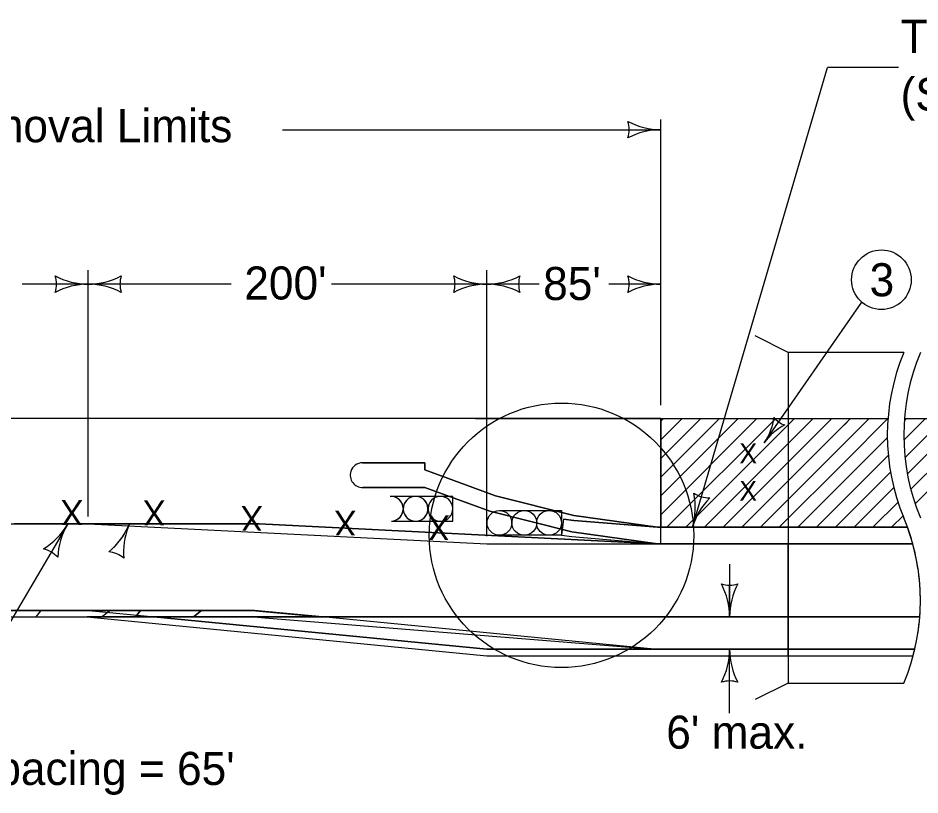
# Model space of a CAD drawing. Extents: x 10133 to 2270741, y 5363 to 1733450.
# Drawn here: x 26557 to 27102, y 11487 to 11957 of the extents above; entities that cross this region are included whole.
import ezdxf

# ---------------------------------------------------------------- set-up
doc = ezdxf.new("R2010")
doc.units = 0
for name, color, linetype in [('dsnNonPlotable', 7, 'Continuous'), ('dsnShtPlotShapeBatchPrint', 7, 'Continuous'), ('dsnStdBlockModified', 7, 'Continuous'), ('dsnStdBorder', 7, 'Continuous'), ('Level 12', 7, 'Continuous'), ('Level 2', 7, 'Continuous')]:
    doc.layers.add(name, color=color, linetype=linetype)

# ---------------------------------------------------------------- blocks, each defined once
blk = doc.blocks.new('LT')
at = {"layer": 'dsnStdBorder'}
for centre, radius, start, end in [((-3.564, 0), 1.642, 342.26665, 17.73335), ((0, 4.25), 4.25, 241.92751, 270), ((0, -4.25), 4.25, 90, 118.07249)]:
    blk.add_arc(centre, radius, start, end, dxfattribs=at)

msp = doc.modelspace()

# ---------------------------------------------------------------- linework, layer by layer
at = {"layer": 'dsnNonPlotable'}
for p, q in [((27022.24, 11754.35), (27002.24, 11764.35)), ((26450.8, 11650.61), (26598.99, 11650.61)), ((26598.99, 11650.61), (26840.04, 11638.61)), ((26943.35, 11648.61), (27094.47, 11648.61)), ((26840.04, 11638.61), (26943.35, 11638.61)), ((27097.65, 11638.61), (26943.35, 11638.61)), ((26598.36, 11594.35), (26924.2, 11594.35)), ((26924.2, 11594.35), (27101.86, 11594.35)), ((26840.04, 11574.84), (27098.85, 11574.84)), ((27022.24, 11554.35), (27002.24, 11544.35))]:
    msp.add_line(p, q, dxfattribs=at)
for points in [[(27092.24, 11754.35), (27022.24, 11754.35), (27022.24, 11554.35), (27092.24, 11554.35)], [(26886.47, 11653.59), (26885.2, 11643.75), (26885.2, 11643.75)], [(26886.47, 11653.59), (26892.7, 11652.78), (26943.35, 11648.61)], [(26885.2, 11643.75), (26891.43, 11642.94), (26943.35, 11638.61)]]:
    msp.add_lwpolyline(points, dxfattribs=at)
for centre, start, end in [((27212.24, 11704.35), 157.3801, 202.6199), ((27222.24, 11704.35), 157.3801, 202.6199), ((26972.24, 11604.35), 337.3801, 22.6199)]:
    msp.add_arc(centre, 130, start, end, dxfattribs=at)
msp.add_open_spline([(26333.01, 11598.33), (26597.17, 11598.33)], degree=1, dxfattribs=at)
at = {"layer": 'dsnShtPlotShapeBatchPrint'}
msp.add_circle((27078.68, 11798.29), 18, dxfattribs=at)
at = {"layer": 'dsnStdBlockModified'}
for p, q in [((26847.69, 11658.75), (26885.2, 11658.75)), ((26885.2, 11658.75), (26885.2, 11643.75)), ((26885.2, 11643.75), (26847.69, 11643.75))]:
    msp.add_line(p, q, dxfattribs=at)
for centre in [(26847.69, 11651.25), (26847.69, 11651.25), (26862.7, 11651.25), (26862.7, 11651.25), (26877.7, 11651.25), (26877.7, 11651.25)]:
    msp.add_circle(centre, 7.5, dxfattribs=at)
at = {"layer": 'dsnStdBorder'}
for p, q in [((26945.31, 11712.79), (26946.86, 11714.35)), ((26945.31, 11701.47), (26958.18, 11714.35)), ((26945.31, 11690.16), (26969.49, 11714.35)), ((26945.31, 11678.85), (26980.81, 11714.35)), ((26945.31, 11667.53), (26992.12, 11714.35)), ((26945.31, 11656.22), (27003.43, 11714.35)), ((26945.31, 11714.35), (26945.31, 11648.61)), ((26949.01, 11648.61), (27014.75, 11714.35)), ((26960.33, 11648.61), (27026.06, 11714.35)), ((26971.64, 11648.61), (27037.37, 11714.35)), ((26982.95, 11648.61), (27048.69, 11714.35)), ((26994.27, 11648.61), (27060, 11714.35)), ((27005.58, 11648.61), (27071.31, 11714.35)), ((27056.08, 11710.38), (27060.04, 11714.35)), ((27056.86, 11688.58), (27082.63, 11714.35)), ((27092.28, 11701.37), (27105.26, 11714.35)), ((27092.53, 11712.93), (27093.94, 11714.35)), ((27092.96, 11690.73), (27116.57, 11714.35)), ((27094.38, 11680.85), (27127.88, 11714.35)), ((27096.44, 11671.59), (27139.2, 11714.35)), ((27099.04, 11662.87), (27150.51, 11714.35)), ((27028.21, 11648.61), (27082.25, 11702.66)), ((27039.52, 11648.61), (27082.84, 11691.93)), ((27016.89, 11648.61), (27056.86, 11688.58)), ((27050.84, 11648.61), (27084.18, 11681.96)), ((27062.15, 11648.61), (27086.17, 11672.64)), ((27073.46, 11648.61), (27088.71, 11663.86)), ((27084.78, 11648.61), (27091.74, 11655.57)), ((26840.04, 11574.84), (26597.17, 11598.33))]:
    msp.add_line(p, q, dxfattribs=at)
for centre, radius in [((26885.2, 11643.75), 80), ((26847.69, 11651.25), 7.5), ((26862.7, 11651.25), 7.5), ((26877.7, 11651.25), 7.5)]:
    msp.add_circle(centre, radius, dxfattribs=at)
at = {"layer": 'Level 12'}
for p, q in [((26964.39, 11648.61), (27046.16, 11926.65)), ((27089, 11926.65), (27046.16, 11926.65)), ((26945.31, 11722.35), (26945.31, 11895.11)), ((26716.55, 11889.05), (26945.31, 11889.05)), ((26598.99, 11655.04), (26598.99, 11804.14)), ((26840.04, 11643.16), (26840.04, 11804.14)), ((26598.99, 11795.63), (26559, 11795.63)), ((26685.41, 11795.63), (26598.99, 11795.63)), ((26840.04, 11795.63), (26746.15, 11795.63)), ((26871.61, 11795.63), (26840.04, 11795.63)), ((26945.31, 11795.63), (26913.74, 11795.63)), ((27007.84, 11699.63), (27066.8, 11784.77)), ((26586.37, 11650.21), (26499.17, 11502.16)), ((26986.89, 11626.35), (26986.89, 11594.35)), ((26976.07, 11594.35), (26994.89, 11594.35)), ((26977.08, 11574.84), (26994.89, 11574.84)), ((26986.89, 11536.08), (26986.89, 11574.84))]:
    msp.add_line(p, q, dxfattribs=at)
for centre, radius, start, end in [((26909.67, 11889.05), 16.42, 342.2666, 17.7334), ((26945.31, 11931.55), 42.5, 241.9275, 270), ((26945.31, 11846.55), 42.5, 90, 118.0725), ((26563.35, 11795.63), 16.42, 342.2666, 17.7334), ((26598.99, 11838.13), 42.5, 241.9275, 270), ((26598.99, 11838.13), 42.5, 270, 298.0725), ((26634.62, 11795.63), 16.42, 162.2666, 197.7334), ((26804.4, 11795.63), 16.42, 342.2666, 17.7334), ((26840.04, 11838.13), 42.5, 241.9275, 270), ((26840.04, 11838.13), 42.5, 270, 298.0725), ((26875.68, 11795.63), 16.42, 162.2666, 197.7334), ((26909.67, 11795.63), 16.42, 342.2666, 17.7334), ((26945.31, 11838.13), 42.5, 241.9275, 270), ((26598.99, 11753.13), 42.5, 90, 118.0725), ((26598.99, 11753.13), 42.5, 61.9275, 90), ((26840.04, 11753.13), 42.5, 90, 118.0725), ((26840.04, 11753.13), 42.5, 61.9275, 90), ((26945.31, 11753.13), 42.5, 90, 118.0725), ((26923.62, 11660.6), 42.5, 343.6131, 11.6856), ((26974.45, 11682.8), 16.42, 235.8797, 271.3464), ((27005.17, 11636.62), 42.5, 135.5406, 163.6131), ((26549.75, 11671.77), 42.5, 301.4319, 329.5044), ((26622.99, 11628.64), 42.5, 149.5044, 177.5769), ((26568.28, 11619.5), 16.42, 41.7711, 77.2378), ((26986.89, 11629.98), 16.42, 252.2666, 287.7333), ((26944.39, 11594.35), 42.5, 360, 28.0725), ((27029.39, 11594.35), 42.5, 151.9275, 180), ((26944.39, 11574.84), 42.5, 331.9275, 360), ((27029.39, 11574.84), 42.5, 180, 208.0725), ((26986.89, 11539.21), 16.42, 72.2666, 107.7334)]:
    msp.add_arc(centre, radius, start, end, dxfattribs=at)
at = {"layer": 'Level 2'}
for p, q in [((26833.17, 11714.35), (26002.51, 11714.35)), ((26833.17, 11714.35), (27082.63, 11714.35)), ((27092.63, 11714.35), (27611.06, 11714.35)), ((26945.31, 11690.16), (26945.31, 11701.47)), ((26802.46, 11683.26), (26802.46, 11687.63)), ((26779.82, 11672.62), (26765.07, 11672.62)), ((26765.07, 11672.62), (26779.82, 11672.62)), ((26794.84, 11672.62), (26780.09, 11672.62)), ((26780.09, 11672.62), (26794.84, 11672.62)), ((26802.46, 11672.62), (26795.08, 11672.62)), ((26795.08, 11672.62), (26802.46, 11672.62)), ((26796.59, 11667.28), (26781.98, 11667.28)), ((26811.6, 11667.28), (26796.59, 11667.28)), ((26819.49, 11667.28), (26811.6, 11667.28)), ((26819.49, 11660.17), (26819.49, 11667.28)), ((26945.31, 11656.22), (26945.31, 11667.53)), ((26819.49, 11652.28), (26819.49, 11659.78)), ((26945.31, 11648.61), (26945.31, 11656.22)), ((26554.11, 11650.61), (26669.49, 11650.61)), ((26702.29, 11650.61), (26554.11, 11650.61)), ((26669.5, 11650.61), (26702.29, 11650.61)), ((26702.29, 11650.61), (26943.35, 11638.61)), ((26943.35, 11638.61), (26702.29, 11650.61)), ((26782.37, 11652.28), (26796.94, 11652.28)), ((26797.38, 11652.28), (26812.38, 11652.28)), ((26812.38, 11652.28), (26819.49, 11652.28)), ((26886.47, 11653.59), (26885.2, 11643.75)), ((26623.71, 11650.21), (26623.1, 11648.67)), ((27094.47, 11648.61), (26943.35, 11648.61)), ((26945.31, 11638.51), (26945.31, 11648.61)), ((26943.35, 11638.61), (27097.65, 11638.61)), ((27022.24, 11638.61), (26943.35, 11638.61)), ((26943.35, 11638.61), (26945.31, 11638.51)), ((27097.65, 11638.61), (27022.24, 11638.61)), ((27022.24, 11638.61), (27022.24, 11594.35)), ((27022.24, 11594.35), (27022.24, 11638.61)), ((26986.89, 11594.35), (26986.89, 11613.57)), ((26630.61, 11598.35), (26394.35, 11598.35)), ((26570.28, 11598.35), (26567.35, 11594.35)), ((26612.14, 11598.35), (26570.28, 11598.35)), ((26607.09, 11594.35), (26612.14, 11598.35)), ((26627.63, 11594.35), (26630.61, 11598.35)), ((26630.61, 11598.35), (26627.63, 11594.35)), ((26667.43, 11598.35), (26630.61, 11598.35)), ((26667.43, 11598.35), (26662.59, 11594.35)), ((26662.59, 11594.35), (26667.43, 11598.35)), ((26698.2, 11598.33), (26739.36, 11594.35)), ((26740.72, 11594.35), (26699.6, 11598.35)), ((26391.11, 11594.35), (26627.63, 11594.35)), ((26567.35, 11594.35), (26607.09, 11594.35)), ((26638.65, 11594.35), (26598.36, 11594.35)), ((26598.36, 11594.35), (26840.04, 11570.84)), ((26598.36, 11594.35), (26840.04, 11570.84)), ((26627.63, 11594.35), (26662.59, 11594.35)), ((26840.04, 11574.84), (26638.65, 11594.35)), ((26924.2, 11594.35), (26638.65, 11594.35)), ((26638.65, 11594.35), (26840.04, 11574.84)), ((26740.72, 11594.35), (26699.4, 11594.35)), ((26699.4, 11594.35), (26705.71, 11593.73)), ((26705.71, 11593.73), (26941.26, 11574.84)), ((26739.36, 11594.35), (26740.72, 11594.35)), ((26941.26, 11574.84), (26740.72, 11594.35)), ((26740.72, 11594.35), (26924.2, 11594.35)), ((27101.86, 11594.35), (27022.24, 11594.35)), ((27022.24, 11594.35), (27022.24, 11574.84)), ((27022.24, 11594.35), (27101.86, 11594.35)), ((27022.24, 11574.84), (27022.24, 11594.35)), ((26986.89, 11574.84), (26840.04, 11574.84)), ((26840.04, 11574.84), (26977.08, 11574.84)), ((26941.27, 11574.84), (27098.85, 11574.84)), ((26977.08, 11574.84), (26986.89, 11574.84)), ((26994.89, 11574.84), (26986.89, 11574.84)), ((26986.89, 11574.84), (26994.89, 11574.84)), ((27022.24, 11574.84), (26994.89, 11574.84)), ((26994.89, 11574.84), (27022.24, 11574.84)), ((27022.24, 11574.84), (27098.85, 11574.84)), ((27022.24, 11570.84), (27022.24, 11574.84)), ((27022.24, 11574.84), (27022.24, 11570.84)), ((27072.51, 11574.84), (27098.85, 11574.84)), ((26840.04, 11570.84), (27097.85, 11570.84)), ((26840.04, 11570.84), (26986.7, 11570.84)), ((26987.08, 11570.84), (27022.24, 11570.84)), ((27071.51, 11570.84), (27097.85, 11570.84))]:
    msp.add_line(p, q, dxfattribs=at)
for points in [[(26945.31, 11714.35), (26904.98, 11714.35), (26833.17, 11714.35)], [(26945.31, 11701.47), (26945.31, 11712.79), (26945.31, 11714.35)], [(26945.31, 11667.53), (26945.31, 11678.85), (26945.31, 11690.16)], [(26764.95, 11687.63), (26764.95, 11687.63), (26794.95, 11687.63), (26794.98, 11687.63), (26802.46, 11687.63)], [(26802.46, 11687.63), (26794.95, 11687.63), (26764.95, 11687.63)], [(26802.46, 11687.63), (26802.46, 11683.26), (26802.46, 11683.26)], [(26802.46, 11683.26), (26845.32, 11667.67), (26892.59, 11655.74), (26943.35, 11648.61), (26945.31, 11648.61)], [(26945.31, 11648.61), (26943.35, 11648.61), (26892.59, 11655.74), (26845.32, 11667.67), (26802.46, 11683.26)], [(26943.35, 11638.61), (26891.41, 11645.87), (26841.9, 11658.27), (26802.46, 11672.62)], [(26802.46, 11672.62), (26841.9, 11658.27), (26891.41, 11645.87), (26943.35, 11638.61)], [(26796.59, 11667.27), (26796.59, 11667.28)], [(26796.59, 11667.28), (26796.59, 11667.27)], [(26811.6, 11667.27), (26811.6, 11667.28)], [(26811.6, 11667.28), (26811.6, 11667.27)], [(26789.47, 11660.17), (26789.49, 11660.17)], [(26804.48, 11660.17), (26804.5, 11660.17)], [(26819.48, 11660.17), (26819.49, 11660.17)], [(26669.49, 11650.61), (26669.5, 11650.61), (26669.75, 11650.95)], [(26782.37, 11652.29), (26782.37, 11652.28)], [(26797.38, 11652.29), (26797.38, 11652.28)], [(26812.38, 11652.29), (26812.38, 11652.28)], [(26812.38, 11652.28), (26812.38, 11652.29)], [(26943.35, 11648.61), (26892.7, 11652.78), (26886.47, 11653.59)], [(26623.1, 11648.67), (26623.04, 11648.7)], [(26885.2, 11643.75), (26891.43, 11642.94), (26943, 11638.64), (26943.35, 11638.61)], [(26943.35, 11638.61), (26943.35, 11638.61)], [(26394.33, 11598.33), (26603.13, 11598.33), (26698.2, 11598.33)], [(26699.6, 11598.35), (26698.64, 11598.35), (26667.43, 11598.35)], [(26662.59, 11594.35), (26699.4, 11594.35), (26740.72, 11594.35)], [(27022.24, 11594.35), (26994.89, 11594.35), (26986.89, 11594.35), (26976.07, 11594.35), (26924.2, 11594.35)], [(26924.2, 11594.35), (26976.07, 11594.35), (26986.89, 11594.35)], [(26986.89, 11594.35), (26994.89, 11594.35), (27022.24, 11594.35)], [(27098.85, 11574.84), (27072.51, 11574.84), (27022.24, 11574.84)], [(27022.24, 11570.84), (27071.51, 11570.84), (27097.85, 11570.84)]]:
    msp.add_lwpolyline(points, dxfattribs=at)
for centre, radius, start, end in [((26764.95, 11680.12), 7.5, 90, 163.0526), ((26764.95, 11680.12), 7.5, 90, 163.0526), ((26764.95, 11680.12), 7.5, 163.0498, 270.9263), ((26764.95, 11680.12), 7.5, 163.0498, 270.9263), ((26779.96, 11680.12), 7.5, 268.9774, 271.0226), ((26779.96, 11680.12), 7.5, 268.9774, 271.0226), ((26794.96, 11680.12), 7.5, 269.0651, 270.9349), ((26794.96, 11680.12), 7.5, 269.0651, 270.9349), ((26781.98, 11659.78), 7.5, 3.0001, 92.9999), ((26781.98, 11659.78), 7.5, 2.9957, 90), ((26796.98, 11659.78), 7.5, 93.0448, 93), ((26796.98, 11659.78), 7.5, 93.0417, 177.0124), ((26796.98, 11659.78), 7.5, 2.9957, 92.9969), ((26811.99, 11659.78), 7.5, 93.006, 182.994), ((26811.99, 11659.78), 7.5, 92.9969, 177.0124), ((26811.98, 11659.77), 7.51, 3.1005, 92.8995), ((26811.99, 11659.78), 7.5, 2.9959, 92.9969), ((26781.96, 11659.83), 7.55, 273.1403, 356.6811), ((26781.96, 11659.83), 7.55, 317.8276, 356.6663), ((26796.98, 11659.78), 7.5, 183.0131, 269.6775), ((26796.96, 11659.83), 7.55, 273.1444, 356.677), ((26796.96, 11659.83), 7.55, 318.902, 356.5996), ((26811.99, 11659.78), 7.5, 182.9958, 273.0042), ((26811.99, 11659.78), 7.5, 183.0813, 273.0025), ((26811.99, 11659.78), 7.5, 272.9998, 3.0002), ((26811.99, 11659.78), 7.5, 273.0025, 0), ((26704.09, 11625.91), 42.5, 143.9182, 144.4611), ((26635.41, 11675.99), 42.5, 323.883, 323.9006), ((26704.09, 11625.91), 42.5, 143.9006, 143.9011), ((26781.98, 11659.78), 7.5, 273.0025, 317.9707), ((26796.98, 11659.78), 7.5, 272.9998, 319.0541), ((26584.51, 11666.64), 42.5, 309.1847, 337.2396), ((26584.51, 11666.64), 42.5, 309.1847, 335.0317), ((26662.9, 11633.78), 42.5, 159.4861, 185.3297), ((26662.9, 11633.78), 42.5, 159.4861, 185.3297), ((26662.9, 11633.78), 42.5, 157.2572, 157.2748), ((26972.24, 11604.35), 130, 15.2823, 19.9072), ((26972.24, 11604.35), 130, 355.5883, 15.2823), ((26609.93, 11617.34), 16.42, 49.5238, 84.9905), ((26609.93, 11617.34), 16.42, 49.5238, 84.9905), ((26986.89, 11629.98), 16.42, 252.2666, 270), ((26944.39, 11594.35), 42.5, 0.0176, 28.0725), ((27029.39, 11594.35), 42.5, 179.9824, 180), ((26972.24, 11604.35), 130, 346.8816, 355.5883), ((26944.39, 11574.84), 42.5, 354.5995, 360), ((26944.39, 11574.84), 42.5, 359.9824, 360), ((27029.39, 11574.84), 42.5, 180.0176, 185.4005), ((26972.24, 11604.35), 130, 345.0644, 346.8816)]:
    msp.add_arc(centre, radius, start, end, dxfattribs=at)

# ---------------------------------------------------------------- block references
at = {"layer": 'Level 12', "xscale": 7.999600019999, "yscale": 7.999200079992, "rotation": -124.70293665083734}
msp.add_blockref('LT', (27007.84, 11699.63), dxfattribs=at)

# ---------------------------------------------------------------- texts
at = {"layer": 'dsnShtPlotShapeBatchPrint'}
msp.add_text('3', height=20, dxfattribs=at).set_placement((27071.54, 11788.29))
at = {"layer": 'dsnStdBorder'}
for p in [(26992.77, 11687.27), (26992.77, 11664.62)]:
    msp.add_text('X', height=12, dxfattribs=at).set_placement(p)
for p in [(26595.86, 11665.05), (26645.61, 11664.86), (26704.64, 11661.52), (26761.16, 11658.72), (26817.69, 11655.91)]:
    msp.add_text('X', height=15, rotation=180, dxfattribs=at).set_placement(p)
at = {"layer": 'Level 12'}
for s, p in [('Temporary Barrier Rail', (27090.28, 11935.5)), ('(See Typical 8210)', (27090.28, 11900.5)), ('Pavement Marking Removal Limits', (26272.94, 11881.46)), ("200'", (26693.38, 11786.34)), ("85'", (26874.13, 11786.02)), ("6' max.", (26948.57, 11514.68)), ("Spacing = 65'", (26525.57, 11492.74))]:
    msp.add_text(s, height=20, dxfattribs=at).set_placement(p)

doc.saveas('drawing.dxf')
